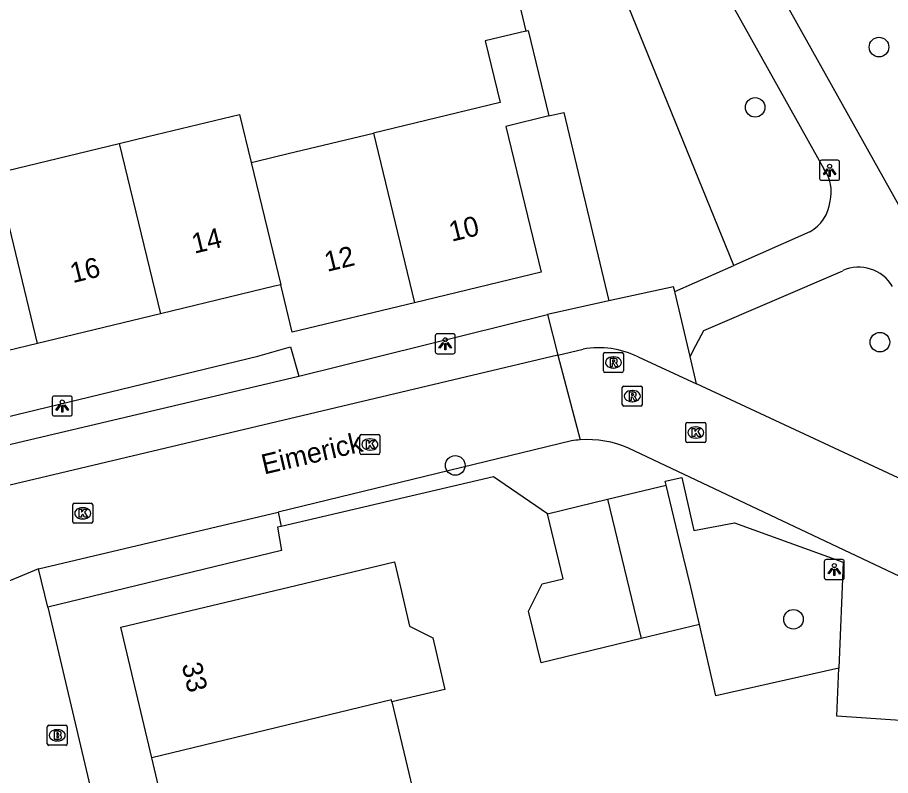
# Model space of a CAD drawing. Extents: x 157793 to 159380, y 380882 to 382313.
# Drawn here: x 158825.72 to 158869.34, y 381240.59 to 381278.47 of the extents above; entities that cross this region are included whole.
import ezdxf

# ---------------------------------------------------------------- set-up
doc = ezdxf.new("R2010")
doc.units = 0
for name, color, linetype in [('IMGEO_Boom', 7, 'Continuous'), ('IMGEO_Brandkraan', 7, 'Continuous'), ('IMGEO_Groenvoorziening', 7, 'Continuous'), ('IMGEO_Kolk', 7, 'Continuous'), ('IMGEO_Lichtpunt', 7, 'Continuous'), ('IMGEO_Muur', 7, 'Continuous'), ('IMGEO_Openbare_ruimte_label', 7, 'Continuous'), ('IMGEO_Pand', 7, 'Continuous'), ('IMGEO_Pand_nummerreeks', 7, 'Continuous'), ('IMGEO_Parkeervlak_open', 7, 'Continuous'), ('IMGEO_Rijbaan_lokaal_open', 7, 'Continuous'), ('IMGEO_Rioolput', 7, 'Continuous'), ('IMGEO_Voetpad_halfverhard', 7, 'Continuous'), ('IMGEO_Voetpad_open', 7, 'Continuous')]:
    doc.layers.add(name, color=color, linetype=linetype)

msp = doc.modelspace()

# ---------------------------------------------------------------- linework, layer by layer
at = {"layer": 'IMGEO_Boom'}
for centre in [(158868.759, 381276.985), (158862.571, 381273.974), (158868.805, 381262.243), (158847.587, 381256.085), (158864.486, 381248.399)]:
    msp.add_circle(centre, 0.489, dxfattribs=at)
at = {"layer": 'IMGEO_Brandkraan'}
for p, q in [((158827.203, 381242.175), (158827.203, 381243.027)), ((158827.278, 381243.101), (158828.13, 381243.101)), ((158828.204, 381243.027), (158828.204, 381242.175)), ((158827.691, 381242.881), (158827.716, 381242.881)), ((158827.714, 381242.321), (158827.689, 381242.321)), ((158828.13, 381242.101), (158827.278, 381242.101))]:
    msp.add_line(p, q, dxfattribs=at)
for points in [[(158827.203, 381242.175), (158827.203, 381243.027)], [(158827.278, 381243.101), (158828.13, 381243.101)], [(158828.204, 381243.027), (158828.204, 381242.175)], [(158827.551, 381242.801), (158827.551, 381242.401), (158827.764, 381242.401)], [(158827.782, 381242.801), (158827.551, 381242.801)], [(158827.73, 381242.72), (158827.676, 381242.72), (158827.676, 381242.644)], [(158827.676, 381242.644), (158827.729, 381242.644)], [(158827.738, 381242.568), (158827.676, 381242.568), (158827.676, 381242.487)], [(158827.676, 381242.487), (158827.738, 381242.487)], [(158828.13, 381242.101), (158827.278, 381242.101)]]:
    msp.add_lwpolyline(points, dxfattribs=at)
for centre, radius, start, end in [((158827.28, 381243.025), 0.0765, 91.552, 178.448), ((158827.28, 381243.025), 0.0765, 91.552, 178.448), ((158828.128, 381243.025), 0.0765, 1.552, 88.448), ((158828.128, 381243.025), 0.0765, 1.552, 88.448), ((158827.731, 381242.682), 0.0379, 267.8285, 90.9355), ((158827.786, 381242.656), 0.145, 59.4692, 91.5367), ((158827.811, 381242.703), 0.0922, 285.5137, 58.1501), ((158827.816, 381242.511), 0.105, 301.3115, 78.989), ((158827.28, 381242.177), 0.0765, 181.552, 268.448), ((158827.28, 381242.177), 0.0765, 181.552, 268.448), ((158827.739, 381242.527), 0.0404, 269.8759, 90.5077), ((158827.77, 381242.652), 0.251, 268.6676, 293.5347), ((158828.128, 381242.177), 0.0765, 271.552, 358.448), ((158828.128, 381242.177), 0.0765, 271.552, 358.448)]:
    msp.add_arc(centre, radius, start, end, dxfattribs=at)
for centre, major_axis, ratio, start_param, end_param in [((158827.69, 381242.601), (-0.387, 0.002), 0.722429, 4.712389, 7.853982), ((158827.715, 381242.601), (-0.39, 0.002), 0.717154, 1.570796, 4.712389)]:
    msp.add_ellipse(centre, major_axis=major_axis, ratio=ratio, start_param=start_param, end_param=end_param, dxfattribs=at)
at = {"layer": 'IMGEO_Groenvoorziening'}
for points in [[(158861.5, 381266.074), (158847.89, 381299.562)], [(158847.502, 381292.957), (158851.122, 381277.783)], [(158852.264, 381273.543), (158853.016, 381273.723), (158855.264, 381264.302)], [(158866.752, 381245.951), (158860.608, 381244.567), (158859.798, 381248.142)]]:
    msp.add_lwpolyline(points, dxfattribs=at)
at = {"layer": 'IMGEO_Kolk'}
for p, q in [((158859.109, 381257.303), (158859.109, 381258.155)), ((158859.184, 381258.229), (158860.036, 381258.229)), ((158859.597, 381258.009), (158859.622, 381258.009)), ((158860.11, 381258.155), (158860.11, 381257.303)), ((158842.827, 381256.706), (158842.827, 381257.558)), ((158842.902, 381257.632), (158843.754, 381257.632)), ((158843.315, 381257.412), (158843.34, 381257.412)), ((158843.828, 381257.558), (158843.828, 381256.706)), ((158859.62, 381257.449), (158859.595, 381257.449)), ((158860.036, 381257.229), (158859.184, 381257.229)), ((158843.754, 381256.632), (158842.902, 381256.632)), ((158843.338, 381256.852), (158843.313, 381256.852)), ((158828.476, 381253.268), (158828.476, 381254.12)), ((158828.551, 381254.194), (158829.403, 381254.194)), ((158828.964, 381253.974), (158828.989, 381253.974)), ((158829.477, 381254.12), (158829.477, 381253.268)), ((158829.403, 381253.194), (158828.551, 381253.194)), ((158828.987, 381253.414), (158828.962, 381253.414))]:
    msp.add_line(p, q, dxfattribs=at)
for points in [[(158859.109, 381257.303), (158859.109, 381258.155)], [(158859.184, 381258.229), (158860.036, 381258.229)], [(158859.43, 381257.929), (158859.553, 381257.929), (158859.553, 381257.778), (158859.683, 381257.929), (158859.847, 381257.929), (158859.701, 381257.778), (158859.854, 381257.529), (158859.702, 381257.529), (158859.617, 381257.693), (158859.553, 381257.626), (158859.553, 381257.529), (158859.43, 381257.529), (158859.43, 381257.929)], [(158860.11, 381258.155), (158860.11, 381257.303)], [(158842.827, 381256.706), (158842.827, 381257.558)], [(158842.902, 381257.632), (158843.754, 381257.632)], [(158843.828, 381257.558), (158843.828, 381256.706)], [(158843.148, 381257.332), (158843.271, 381257.332), (158843.271, 381257.181), (158843.401, 381257.332), (158843.565, 381257.332), (158843.419, 381257.181), (158843.572, 381256.932), (158843.42, 381256.932), (158843.335, 381257.096), (158843.271, 381257.029), (158843.271, 381256.932), (158843.148, 381256.932), (158843.148, 381257.332)], [(158860.036, 381257.229), (158859.184, 381257.229)], [(158843.754, 381256.632), (158842.902, 381256.632)], [(158828.476, 381253.268), (158828.476, 381254.12)], [(158828.551, 381254.194), (158829.403, 381254.194)], [(158829.477, 381254.12), (158829.477, 381253.268)], [(158828.797, 381253.894), (158828.92, 381253.894), (158828.92, 381253.743), (158829.05, 381253.894), (158829.214, 381253.894), (158829.068, 381253.743), (158829.221, 381253.494), (158829.069, 381253.494), (158828.984, 381253.658), (158828.92, 381253.591), (158828.92, 381253.494), (158828.797, 381253.494), (158828.797, 381253.894)], [(158829.403, 381253.194), (158828.551, 381253.194)]]:
    msp.add_lwpolyline(points, dxfattribs=at)
for centre, start, end in [((158859.186, 381258.153), 91.552, 178.448), ((158859.186, 381258.153), 91.552, 178.448), ((158860.034, 381258.153), 1.552, 88.448), ((158860.034, 381258.153), 1.552, 88.448), ((158842.904, 381257.556), 91.552, 178.448), ((158842.904, 381257.556), 91.552, 178.448), ((158843.752, 381257.556), 1.552, 88.448), ((158843.752, 381257.556), 1.552, 88.448), ((158859.186, 381257.305), 181.552, 268.448), ((158859.186, 381257.305), 181.552, 268.448), ((158860.034, 381257.305), 271.552, 358.448), ((158860.034, 381257.305), 271.552, 358.448), ((158842.904, 381256.708), 181.552, 268.448), ((158842.904, 381256.708), 181.552, 268.448), ((158843.752, 381256.708), 271.552, 358.448), ((158843.752, 381256.708), 271.552, 358.448), ((158828.553, 381254.118), 91.552, 178.448), ((158828.553, 381254.118), 91.552, 178.448), ((158829.401, 381254.118), 1.552, 88.448), ((158829.401, 381254.118), 1.552, 88.448), ((158828.553, 381253.27), 181.552, 268.448), ((158828.553, 381253.27), 181.552, 268.448), ((158829.401, 381253.27), 271.552, 358.448), ((158829.401, 381253.27), 271.552, 358.448)]:
    msp.add_arc(centre, 0.0765, start, end, dxfattribs=at)
for centre, major_axis, ratio, start_param, end_param in [((158859.596, 381257.729), (-0.387, 0.002), 0.722429, 4.712389, 7.853982), ((158859.621, 381257.729), (-0.39, 0.002), 0.717154, 1.570796, 4.712389), ((158843.314, 381257.132), (-0.387, 0.002), 0.722429, 4.712389, 7.853982), ((158843.339, 381257.132), (-0.39, 0.002), 0.717154, 1.570796, 4.712389), ((158828.963, 381253.694), (-0.387, 0.002), 0.722429, 4.712389, 7.853982), ((158828.988, 381253.694), (-0.39, 0.002), 0.717154, 1.570796, 4.712389)]:
    msp.add_ellipse(centre, major_axis=major_axis, ratio=ratio, start_param=start_param, end_param=end_param, dxfattribs=at)
at = {"layer": 'IMGEO_Lichtpunt'}
for p, q in [((158865.793, 381271.234), (158865.793, 381270.427)), ((158865.793, 381271.234), (158865.793, 381270.427)), ((158866.695, 381271.329), (158865.887, 381271.329)), ((158866.695, 381271.329), (158865.887, 381271.329)), ((158866.789, 381270.427), (158866.789, 381271.234)), ((158866.789, 381270.427), (158866.789, 381271.234)), ((158865.887, 381270.333), (158866.695, 381270.333)), ((158865.887, 381270.333), (158866.695, 381270.333)), ((158847.491, 381262.66), (158846.683, 381262.66)), ((158847.491, 381262.66), (158846.683, 381262.66)), ((158846.589, 381262.565), (158846.589, 381261.758)), ((158846.589, 381262.565), (158846.589, 381261.758)), ((158847.585, 381261.758), (158847.585, 381262.565)), ((158847.585, 381261.758), (158847.585, 381262.565)), ((158846.683, 381261.664), (158847.491, 381261.664)), ((158846.683, 381261.664), (158847.491, 381261.664)), ((158827.453, 381259.457), (158827.453, 381258.65)), ((158827.453, 381259.457), (158827.453, 381258.65)), ((158828.355, 381259.552), (158827.547, 381259.552)), ((158828.355, 381259.552), (158827.547, 381259.552)), ((158828.449, 381258.65), (158828.449, 381259.457)), ((158828.449, 381258.65), (158828.449, 381259.457)), ((158827.547, 381258.556), (158828.355, 381258.556)), ((158827.547, 381258.556), (158828.355, 381258.556)), ((158866.928, 381251.382), (158866.12, 381251.382)), ((158866.928, 381251.382), (158866.12, 381251.382)), ((158866.026, 381251.287), (158866.026, 381250.48)), ((158866.026, 381251.287), (158866.026, 381250.48)), ((158867.022, 381250.48), (158867.022, 381251.287)), ((158867.022, 381250.48), (158867.022, 381251.287)), ((158866.12, 381250.386), (158866.928, 381250.386)), ((158866.12, 381250.386), (158866.928, 381250.386))]:
    msp.add_line(p, q, dxfattribs=at)
for points in [[(158866.167, 381270.898), (158866.206, 381270.87), (158866.018, 381270.608), (158865.98, 381270.635), (158866.167, 381270.898)], [(158866.269, 381270.85), (158866.316, 381270.85), (158866.316, 381270.528), (158866.269, 381270.528), (158866.269, 381270.85)], [(158866.379, 381270.87), (158866.417, 381270.897), (158866.604, 381270.635), (158866.565, 381270.607), (158866.379, 381270.87)], [(158846.963, 381262.229), (158847.002, 381262.201), (158846.814, 381261.939), (158846.776, 381261.966), (158846.963, 381262.229)], [(158847.175, 381262.201), (158847.213, 381262.228), (158847.4, 381261.966), (158847.361, 381261.938), (158847.175, 381262.201)], [(158847.065, 381262.181), (158847.112, 381262.181), (158847.112, 381261.859), (158847.065, 381261.859), (158847.065, 381262.181)], [(158827.827, 381259.121), (158827.866, 381259.093), (158827.678, 381258.831), (158827.64, 381258.858), (158827.827, 381259.121)], [(158827.929, 381259.073), (158827.976, 381259.073), (158827.976, 381258.751), (158827.929, 381258.751), (158827.929, 381259.073)], [(158828.039, 381259.093), (158828.077, 381259.12), (158828.264, 381258.858), (158828.225, 381258.83), (158828.039, 381259.093)], [(158866.4, 381250.951), (158866.439, 381250.923), (158866.251, 381250.661), (158866.213, 381250.688), (158866.4, 381250.951)], [(158866.502, 381250.903), (158866.549, 381250.903), (158866.549, 381250.581), (158866.502, 381250.581), (158866.502, 381250.903)], [(158866.612, 381250.923), (158866.65, 381250.95), (158866.837, 381250.688), (158866.798, 381250.66), (158866.612, 381250.923)]]:
    msp.add_lwpolyline(points, dxfattribs=at)
for centre in [(158866.292, 381271.032), (158847.088, 381262.363), (158827.952, 381259.255), (158866.525, 381251.085)]:
    msp.add_circle(centre, 0.0994, dxfattribs=at)
for centre, start, end in [((158865.887, 381271.234), 90, 180), ((158865.887, 381271.234), 90, 180), ((158866.695, 381271.234), 0, 90), ((158866.695, 381271.234), 0, 90), ((158865.887, 381270.427), 180, 270), ((158865.887, 381270.427), 180, 270), ((158866.695, 381270.427), 270, 0), ((158866.695, 381270.427), 270, 360), ((158846.683, 381262.565), 90, 180), ((158846.683, 381262.565), 90, 180), ((158847.491, 381262.565), 0, 90), ((158847.491, 381262.565), 0, 90), ((158846.683, 381261.758), 180, 270), ((158846.683, 381261.758), 180, 270), ((158847.491, 381261.758), 270, 0), ((158847.491, 381261.758), 270, 360), ((158827.547, 381259.457), 90, 180), ((158827.547, 381259.457), 90, 180), ((158828.355, 381259.457), 0, 90), ((158828.355, 381259.457), 0, 90), ((158827.547, 381258.65), 180, 270), ((158827.547, 381258.65), 180, 270), ((158828.355, 381258.65), 270, 0), ((158828.355, 381258.65), 270, 360), ((158866.12, 381251.287), 90, 180), ((158866.12, 381251.287), 90, 180), ((158866.928, 381251.287), 0, 90), ((158866.928, 381251.287), 0, 90), ((158866.12, 381250.48), 180, 270), ((158866.12, 381250.48), 180, 270), ((158866.928, 381250.48), 270, 0), ((158866.928, 381250.48), 270, 360)]:
    msp.add_arc(centre, 0.0946, start, end, dxfattribs=at)
at = {"layer": 'IMGEO_Muur'}
for points in [[(158852.189, 381253.672), (158849.504, 381255.511), (158838.898, 381253.04)], [(158838.898, 381253.04), (158838.707, 381252.995), (158838.908, 381251.84)]]:
    msp.add_lwpolyline(points, dxfattribs=at)
at = {"layer": 'IMGEO_Pand'}
for points in [[(158851.122, 381277.783), (158849.084, 381277.291), (158849.826, 381274.221), (158843.504, 381272.693)], [(158851.122, 381277.783), (158851.232, 381277.81), (158852.264, 381273.543)], [(158830.794, 381272.172), (158832.229, 381272.519), (158836.809, 381273.625), (158837.392, 381271.216)], [(158852.264, 381273.543), (158850.115, 381273.023), (158851.875, 381265.743), (158845.554, 381264.215)], [(158837.392, 381271.216), (158837.671, 381271.283), (158839.235, 381271.661), (158843.504, 381272.693)], [(158843.504, 381272.693), (158845.554, 381264.215)], [(158824.659, 381270.689), (158830.794, 381272.172)], [(158830.794, 381272.172), (158832.855, 381263.656)], [(158837.392, 381271.216), (158838.869, 381265.109)], [(158826.718, 381262.173), (158824.659, 381270.689)], [(158838.869, 381265.109), (158838.554, 381265.033), (158836.847, 381264.62), (158832.855, 381263.656)], [(158845.554, 381264.215), (158839.443, 381262.738), (158838.869, 381265.109)], [(158832.855, 381263.656), (158826.718, 381262.173)], [(158826.718, 381262.173), (158820.642, 381260.704)], [(158855.195, 381254.398), (158858.119, 381255.104)], [(158859.798, 381248.142), (158859.35, 381250), (158858.793, 381252.311), (158858.119, 381255.104)], [(158852.189, 381253.672), (158855.195, 381254.398)], [(158855.195, 381254.398), (158856.878, 381247.437)], [(158856.878, 381247.437), (158851.876, 381246.229), (158851.254, 381248.805), (158851.854, 381250), (158851.936, 381250.164), (158852.975, 381250.415), (158852.189, 381253.672)], [(158832.424, 381241.479), (158830.884, 381248.001), (158839.268, 381250), (158844.556, 381251.261), (158844.849, 381250), (158845.304, 381248.047), (158846.465, 381247.463), (158847.066, 381244.882), (158844.428, 381244.269)], [(158859.798, 381248.142), (158856.878, 381247.437)], [(158844.428, 381244.269), (158844.401, 381244.382), (158840.755, 381243.486), (158832.424, 381241.479)], [(158844.428, 381244.269), (158845.515, 381239.663), (158845.773, 381238.57), (158845.841, 381238.289)], [(158837.638, 381236.313), (158833.858, 381235.402), (158832.424, 381241.479)]]:
    msp.add_lwpolyline(points, dxfattribs=at)
at = {"layer": 'IMGEO_Parkeervlak_open'}
for points in [[(158839.777, 381260.543), (158852.203, 381263.63)], [(158838.898, 381253.04), (158838.707, 381252.995), (158838.908, 381251.84), (158827.234, 381249.01)]]:
    msp.add_lwpolyline(points, dxfattribs=at)
at = {"layer": 'IMGEO_Rijbaan_lokaal_open'}
for points in [[(158852.721, 381261.601), (158853.976, 381261.897)], [(158852.721, 381261.601), (158817.745, 381253.299)], [(158852.721, 381261.601), (158853.829, 381257.361)], [(158856.73, 381261.505), (158859.641, 381260.157)], [(158873.895, 381253.511), (158859.641, 381260.157)], [(158853.391, 381257.309), (158838.745, 381253.748)], [(158872.554, 381249.232), (158856.241, 381256.942)], [(158826.763, 381250.912), (158838.745, 381253.748)], [(158826.763, 381250.912), (158822.393, 381249.104)], [(158827.234, 381249.01), (158826.763, 381250.912)], [(158827.234, 381249.01), (158832.763, 381225.547), (158831.574, 381225.304), (158835.965, 381206.655)]]:
    msp.add_lwpolyline(points, dxfattribs=at)
for centre, radius, start, end in [((158854.749, 381257.461), 4.503, 63.9071, 99.8909), ((158854.174, 381252.587), 4.787, 94.1299, 99.4112), ((158854.203, 381252.364), 5.011, 66.007, 94.2835)]:
    msp.add_arc(centre, radius, start, end, dxfattribs=at)
at = {"layer": 'IMGEO_Rioolput'}
for p, q in [((158854.99, 381260.803), (158854.99, 381261.655)), ((158855.065, 381261.729), (158855.917, 381261.729)), ((158855.478, 381261.509), (158855.503, 381261.509)), ((158855.991, 381261.655), (158855.991, 381260.803)), ((158855.501, 381260.949), (158855.476, 381260.949)), ((158855.917, 381260.729), (158855.065, 381260.729)), ((158856.009, 381260.049), (158856.861, 381260.049)), ((158855.934, 381259.123), (158855.934, 381259.975)), ((158856.422, 381259.829), (158856.447, 381259.829)), ((158856.935, 381259.975), (158856.935, 381259.123)), ((158856.445, 381259.269), (158856.42, 381259.269)), ((158856.861, 381259.049), (158856.009, 381259.049))]:
    msp.add_line(p, q, dxfattribs=at)
for points in [[(158854.99, 381260.803), (158854.99, 381261.655)], [(158855.065, 381261.729), (158855.917, 381261.729)], [(158855.579, 381261.427), (158855.327, 381261.429), (158855.327, 381261.029)], [(158855.505, 381261.348), (158855.451, 381261.348), (158855.451, 381261.267)], [(158855.991, 381261.655), (158855.991, 381260.803)], [(158855.327, 381261.029), (158855.451, 381261.029), (158855.451, 381261.191), (158855.462, 381261.191)], [(158855.451, 381261.267), (158855.503, 381261.267)], [(158855.509, 381261.162), (158855.58, 381261.029), (158855.72, 381261.029), (158855.655, 381261.155)], [(158855.917, 381260.729), (158855.065, 381260.729)], [(158856.009, 381260.049), (158856.861, 381260.049)], [(158855.934, 381259.123), (158855.934, 381259.975)], [(158856.523, 381259.747), (158856.271, 381259.749), (158856.271, 381259.349)], [(158856.449, 381259.668), (158856.395, 381259.668), (158856.395, 381259.587)], [(158856.395, 381259.587), (158856.447, 381259.587)], [(158856.935, 381259.975), (158856.935, 381259.123)], [(158856.271, 381259.349), (158856.395, 381259.349), (158856.395, 381259.511), (158856.406, 381259.511)], [(158856.453, 381259.482), (158856.524, 381259.349), (158856.664, 381259.349), (158856.599, 381259.475)], [(158856.861, 381259.049), (158856.009, 381259.049)]]:
    msp.add_lwpolyline(points, dxfattribs=at)
for centre, radius, start, end in [((158855.067, 381261.653), 0.0765, 91.552, 178.448), ((158855.067, 381261.653), 0.0765, 91.552, 178.448), ((158855.511, 381261.252), 0.0964, 77.0061, 93.1865), ((158855.525, 381261.309), 0.0378, 276.6634, 79.6772), ((158855.578, 381261.317), 0.109, 350.3612, 89.416), ((158855.915, 381261.653), 0.0765, 1.552, 88.448), ((158855.915, 381261.653), 0.0765, 1.552, 88.448), ((158855.461, 381261.138), 0.0533, 26.0293, 88.6989), ((158855.487, 381261.456), 0.19, 274.7715, 282.9687), ((158855.576, 381261.317), 0.112, 277.5842, 350.9817), ((158855.56, 381261.102), 0.108, 29.5134, 73.7905), ((158855.067, 381260.805), 0.0765, 181.552, 268.448), ((158855.067, 381260.805), 0.0765, 181.552, 268.448), ((158855.915, 381260.805), 0.0765, 271.552, 358.448), ((158855.915, 381260.805), 0.0765, 271.552, 358.448), ((158856.011, 381259.973), 0.0765, 91.552, 178.448), ((158856.011, 381259.973), 0.0765, 91.552, 178.448), ((158856.859, 381259.973), 0.0765, 1.552, 88.448), ((158856.859, 381259.973), 0.0765, 1.552, 88.448), ((158856.431, 381259.776), 0.19, 274.7715, 282.9687), ((158856.455, 381259.572), 0.0964, 77.0061, 93.1865), ((158856.469, 381259.629), 0.0378, 276.6634, 79.6772), ((158856.522, 381259.637), 0.109, 350.3612, 89.416), ((158856.52, 381259.637), 0.112, 277.5842, 350.9817), ((158856.405, 381259.458), 0.0533, 26.0293, 88.6989), ((158856.504, 381259.422), 0.108, 29.5134, 73.7905), ((158856.011, 381259.125), 0.0765, 181.552, 268.448), ((158856.011, 381259.125), 0.0765, 181.552, 268.448), ((158856.859, 381259.125), 0.0765, 271.552, 358.448), ((158856.859, 381259.125), 0.0765, 271.552, 358.448)]:
    msp.add_arc(centre, radius, start, end, dxfattribs=at)
for centre, major_axis, ratio, start_param, end_param in [((158855.477, 381261.229), (-0.387, 0.002), 0.722429, 4.712389, 7.853982), ((158855.502, 381261.229), (-0.39, 0.002), 0.717154, 1.570796, 4.712389), ((158856.421, 381259.549), (-0.387, 0.002), 0.722429, 4.712389, 7.853982), ((158856.446, 381259.549), (-0.39, 0.002), 0.717154, 1.570796, 4.712389)]:
    msp.add_ellipse(centre, major_axis=major_axis, ratio=ratio, start_param=start_param, end_param=end_param, dxfattribs=at)
at = {"layer": 'IMGEO_Voetpad_halfverhard'}
for points in [[(158847.89, 381299.562), (158849.737, 381300.005), (158865.999, 381270.903)], [(158880.077, 381250.629), (158861.545, 381283.771)], [(158865.298, 381267.758), (158861.5, 381266.074)], [(158858.557, 381264.77), (158861.5, 381266.074)], [(158859.319, 381261.529), (158859.613, 381262.079), (158860.008, 381262.818), (158866.945, 381265.815)]]:
    msp.add_lwpolyline(points, dxfattribs=at)
for centre, radius, start, end in [((158864.472, 381269.762), 1.906, 345.3991, 36.7857), ((158864.328, 381269.509), 2.002, 298.972, 353.4571), ((158867.749, 381264.042), 1.947, 30.2667, 114.3912)]:
    msp.add_arc(centre, radius, start, end, dxfattribs=at)
at = {"layer": 'IMGEO_Voetpad_open'}
for points in [[(158858.557, 381264.77), (158858.5, 381265.012), (158855.264, 381264.302)], [(158859.319, 381261.529), (158858.557, 381264.77)], [(158855.264, 381264.302), (158852.203, 381263.63)], [(158852.203, 381263.63), (158852.721, 381261.601)], [(158802.796, 381251.794), (158815.989, 381254.97), (158815.631, 381256.192), (158837.72, 381261.543), (158839.36, 381262.015), (158839.777, 381260.543)], [(158859.641, 381260.157), (158859.319, 381261.529)], [(158817.745, 381253.299), (158817.332, 381255.25), (158839.777, 381260.543)], [(158852.189, 381253.672), (158849.504, 381255.511), (158838.898, 381253.04)], [(158858.119, 381255.104), (158858.071, 381255.292), (158858.905, 381255.487), (158859.513, 381252.827), (158861.541, 381253.22), (158866.961, 381251.253), (158866.752, 381245.951)], [(158838.745, 381253.748), (158838.898, 381253.04)], [(158885.275, 381243.32), (158878.143, 381241.655), (158877.854, 381242.8), (158866.657, 381243.554), (158866.752, 381245.951)]]:
    msp.add_lwpolyline(points, dxfattribs=at)

# ---------------------------------------------------------------- texts
at = {"layer": 'IMGEO_Openbare_ruimte_label'}
msp.add_text('Eimerick', height=1, rotation=13.1191, dxfattribs=at).set_placement((158838.038, 381255.628))
at = {"layer": 'IMGEO_Pand_nummerreeks'}
for s, rotation, p in [('10', 13.5906, (158847.41, 381267.257)), ('14', 13.5848, (158834.555, 381266.659)), ('12', 13.5906, (158841.188, 381265.752)), ('16', 13.5864, (158828.48, 381265.191)), ('33', 283.2822, (158833.916, 381246.123))]:
    msp.add_text(s, height=1, rotation=rotation, dxfattribs=at).set_placement(p)

doc.saveas('drawing.dxf')
